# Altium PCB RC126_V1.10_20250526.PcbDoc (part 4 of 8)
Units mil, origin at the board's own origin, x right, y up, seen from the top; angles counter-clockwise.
Board outline 6299.62 x 3544.12 mil, 4 copper layers (Top, GND, Power, Bottom), stack 35.4 mil thick; 509 components, 417 nets, 1867 pads, 2150 vias.
Unrouted connection lines stored in the file: 1451.
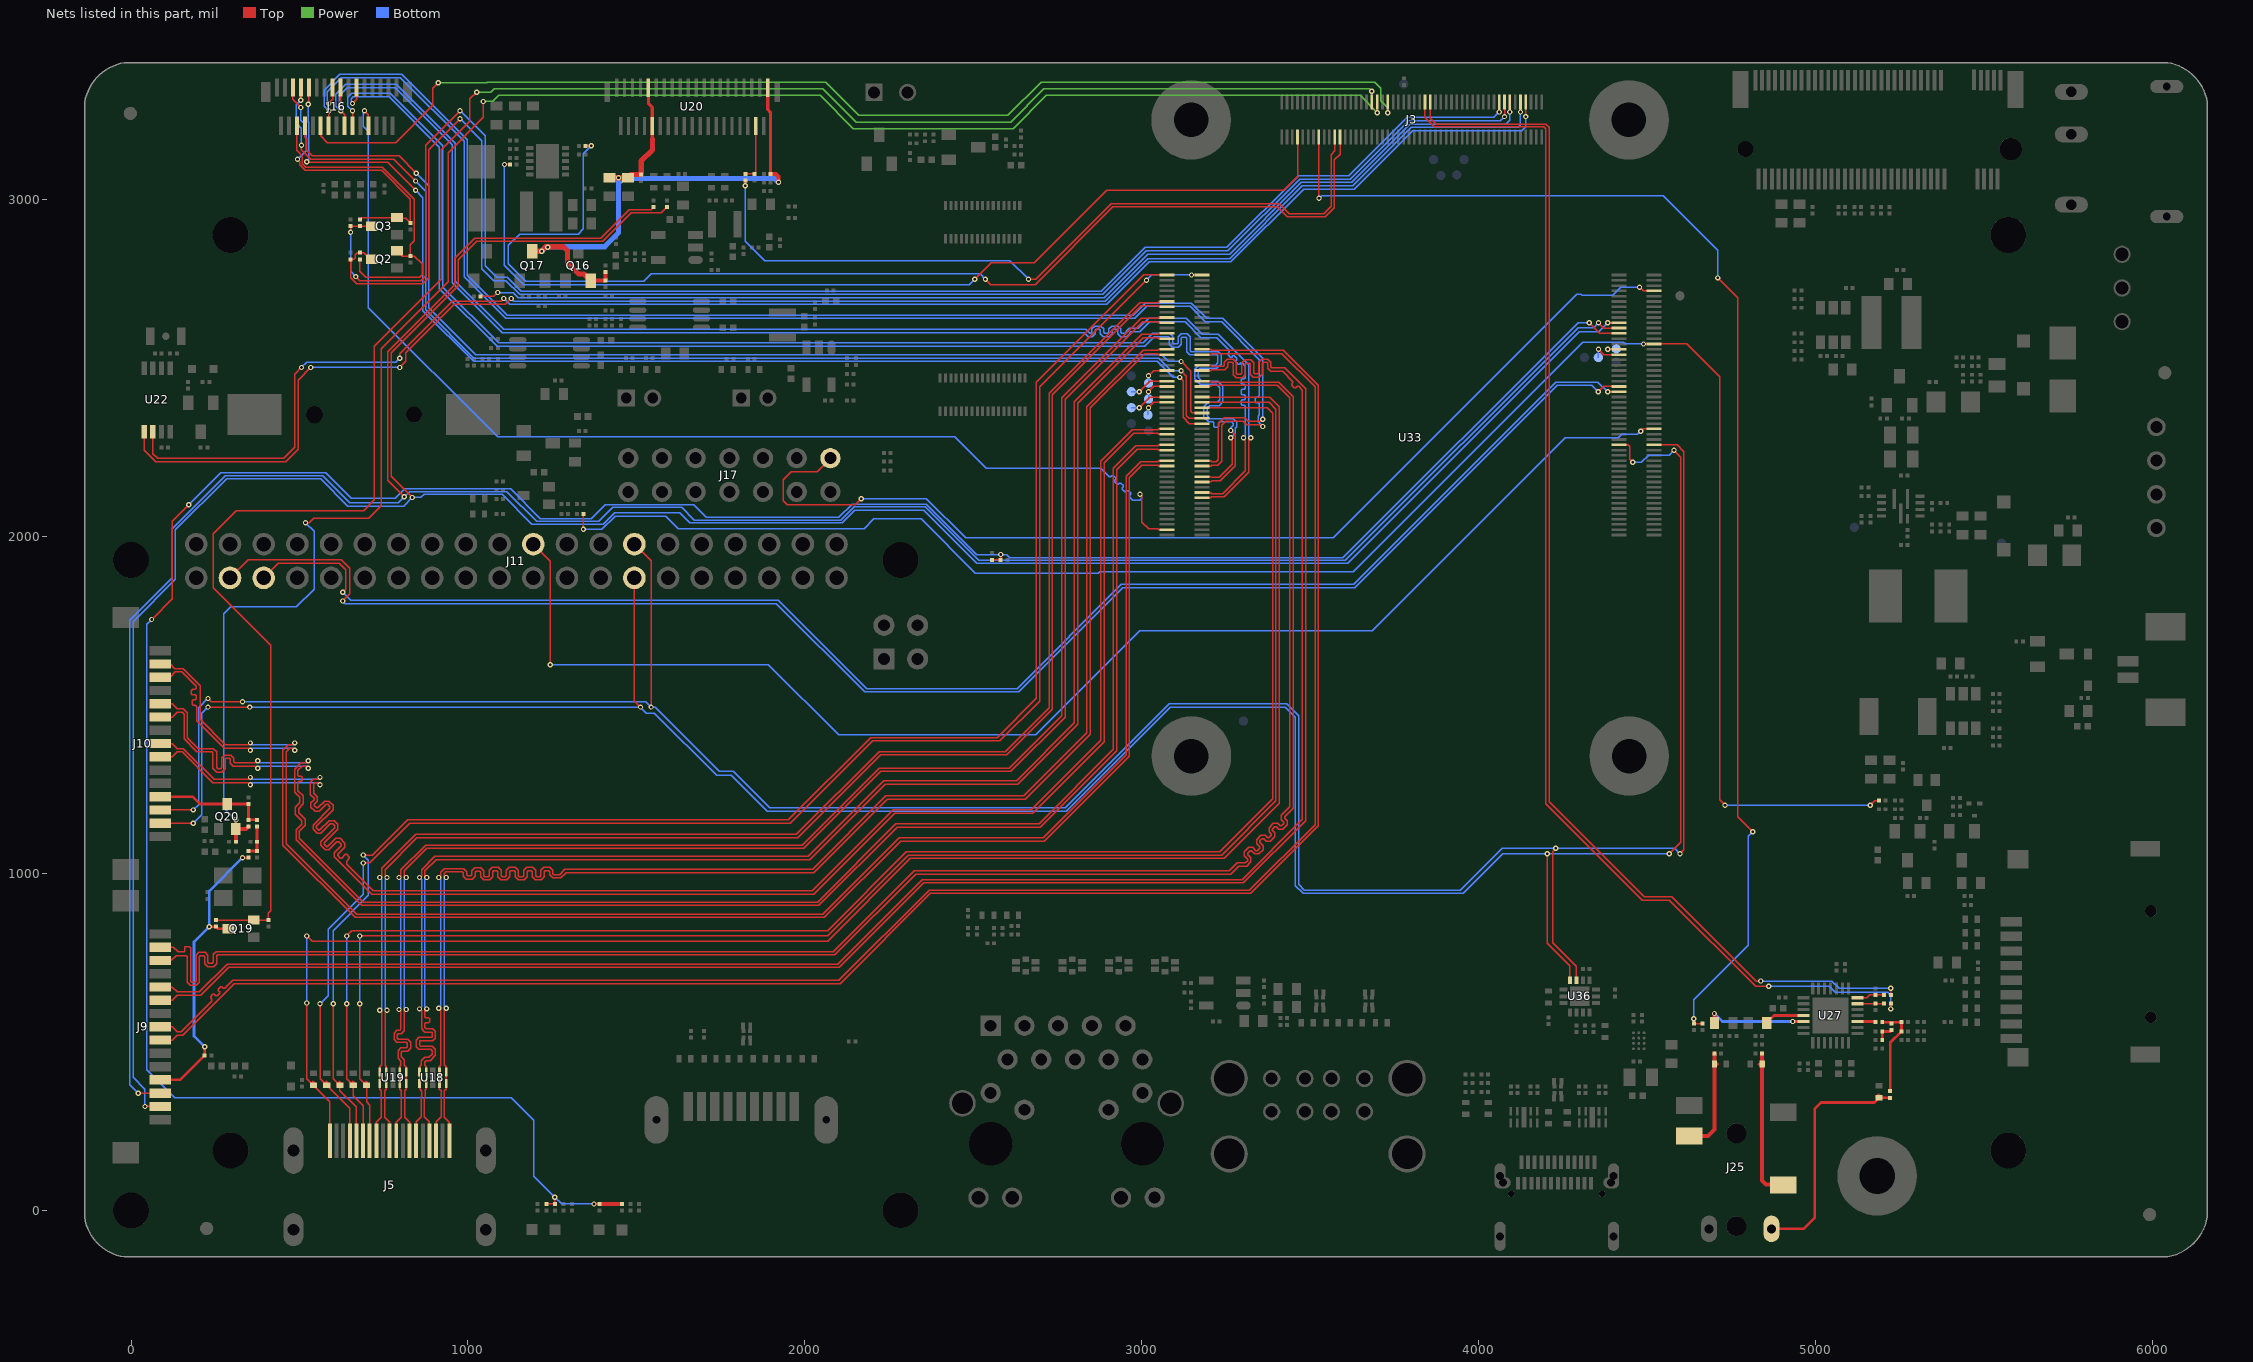
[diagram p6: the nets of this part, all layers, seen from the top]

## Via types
v1: diameter 15.75, hole 7.87, Top to Bottom, 2047 vias
v2: diameter 19.68, hole 11.81, Top to Bottom, 103 vias

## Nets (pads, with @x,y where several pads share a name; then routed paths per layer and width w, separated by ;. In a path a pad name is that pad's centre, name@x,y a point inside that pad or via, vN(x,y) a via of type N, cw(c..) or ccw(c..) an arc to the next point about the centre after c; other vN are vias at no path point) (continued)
GPIO3_D6_1V8: R326.1 R356.1 U33.73 | length 5594.9
  Top w3.94: v1(1342.52,2021.65) R356.1@1342.52,2066.93 ; v1(4488.58,2571.65) U33.73@4520.08,2571.65 4617.32,2571.65 4714.57,2474.41 4714.57,1218.5 v1(4730.32,1202.76) ; v1(5161.42,1202.76) 5175.2,1216.54 R326.1@5187.01,1216.54
  Bottom w3.94: v1(1342.52,2021.65) 1397.64,2021.65 1437.01,2061.02 1586.61,2061.02 1624.02,2023.62 2175.2,2023.62 2204.72,2053.15 2344.49,2053.15 2505.91,1891.73 2870.2,1891.73 2874.14,1895.67 3627.13,1895.67 4308.23,2576.77 4428.78,2576.77 4433.9,2571.65 v1(4488.58,2571.65) ; v1(4730.32,1202.76) v1(5161.42,1202.76)
GPIO_VREF: R214.1 R215.1 R216.2 R219.1 R224.1 R225.2 U33.78 | length 8265.5
  Top w3.94: v1(61.02,1753.94) 122.05,1814.96 122.05,2045.28 v1(171.26,2094.49) ; R219.1@1232.28,19.69 R216.2@1257.87,19.69 v1(1257.87,39.37) ; v1(1374.02,19.69) R224.1@1389.76,19.69 ; R215.1@2555.12,1931.1 R214.1@2580.71,1931.1 v1(2580.71,1946.85) ; v1(4327.17,2634.65) 4358.66,2603.15 U33.78@4415.35,2603.15
  Top w11.81: R224.1@1389.76,19.69 R225.2@1456.69,19.69
  Bottom w3.94: v1(61.02,1753.94) 47.24,1740.16 47.24,417.32 129.92,334.65 1127.95,334.65 1194.88,267.72 1194.88,102.36 v1(1257.87,39.37) 1277.56,19.69 v1(1374.02,19.69) ; v1(171.26,2094.49) 265.75,2188.98 578.13,2188.98 652.93,2114.17 784.02,2114.17 811.58,2141.73 1126.35,2141.73 1214.93,2053.15 1366.38,2053.15 1407.72,2094.49 1669.88,2094.49 1707.28,2057.09 2100.92,2057.09 2140.29,2096.46 2360.24,2096.46 2509.84,1946.85 v1(2580.71,1946.85) 2598.12,1946.85 2607.96,1937.01 3596.46,1937.01 4294.09,2634.65 v1(4327.17,2634.65)
HDMI_TX0N: J5.9 U19.4 U19.7 U33.184 | length 4399.1
  Top w3.94: J5.9@787.09,207.82 787.09,261.5 802.16,276.57 802.16,355.31 797.24,360.24 U19.4@797.24,376.48 U19.7@797.24,410.92 797.24,427.17 801.18,431.11 801.18,443.83 792.32,452.69 792.32,474.55 801.04,483.27 816.93,483.27 819.88,486.22 819.88,496.06 816.93,499.02 789.23,499.02 780.51,507.73 780.51,525.73 789.23,534.45 798.23,534.45 801.18,537.4 801.18,590.55 v1(795.28,596.46) ; v1(795.28,988.19) 801.18,994.09 801.18,1011.81 874.02,1084.65 1992.13,1084.65 2220.47,1312.99 2606.3,1312.99 2761.81,1468.5 2761.81,2411.42 2997.83,2647.44 3046.26,2647.44 3049.21,2650.39 U33.184@3074.8,2650.39
  Bottom w3.94: v1(795.28,596.46) 801.18,602.36 801.18,982.28 v1(795.28,988.19)
HDMI_TX0P: J5.7 U19.5 U19.6 U33.182 | length 4383.4
  Top w3.94: v1(816.93,596.46) 811.02,590.55 811.02,533.32 802.31,524.61 793.31,524.61 790.35,521.65 790.35,511.81 793.31,508.86 821.01,508.86 829.72,500.14 829.72,482.14 821.01,473.43 805.12,473.43 802.17,470.47 802.17,456.76 811.02,447.9 811.02,431.1 816.93,425.2 U19.6@816.93,410.92 U19.5@816.93,376.48 816.93,360.24 812.01,355.31 812.01,276.58 826.46,262.13 J5.7@826.46,207.82 ; v1(816.93,988.19) 811.02,994.09 811.02,1007.73 878.09,1074.8 1996.2,1074.8 2224.55,1303.15 2610.38,1303.15 2771.65,1464.43 2771.65,2407.34 3001.91,2637.6 3046.26,2637.6 3049.21,2634.65 U33.182@3074.8,2634.65
  Bottom w3.94: v1(816.93,596.46) 811.02,602.36 811.02,982.28 v1(816.93,988.19)
HDMI_TX1N: J5.6 U18.1 U18.10 U33.178 | length 4383.8
  Top w3.94: J5.6@846.14,207.82 846.14,263.46 860.9,278.22 860.9,337.28 863.19,339.57 863.19,354.34 856.3,361.22 U18.1@856.3,376.48 U18.10@856.3,410.92 856.3,427.17 861.22,432.09 861.22,443.9 872.05,454.72 883.86,454.72 893.7,464.57 893.7,474.41 889.76,478.35 861.08,478.35 854.19,478.35 846.46,486.08 846.46,506.05 854.19,513.78 859.11,513.78 891.73,513.78 893.7,515.75 893.7,527.56 891.73,529.53 871.91,529.53 862.2,539.23 862.2,592.52 v1(856.3,598.43) ; v1(856.3,988.19) 862.2,994.09 862.2,1011.81 901.57,1051.18 2009.84,1051.18 2234.25,1275.59 2627.81,1275.59 2799.21,1446.99 2799.21,2399.61 2999.8,2600.2 3046.26,2600.2 3049.21,2603.15 U33.178@3074.8,2603.15
  Bottom w3.94: v1(856.3,598.43) 862.2,604.33 862.2,982.28 ; v1(856.3,988.19) 862.2,982.28 ; v1@862.2,983.59 862.2,982.28
HDMI_TX1P: J5.4 U18.2 U18.9 U33.176 | length 4385.2
  Top w3.94: v1(877.95,598.43) 872.05,592.52 872.05,574.8 874.02,572.83 881.89,572.83 885.83,568.9 885.83,561.02 881.89,557.09 874.02,557.09 872.05,555.12 872.05,543.31 875.98,539.37 895.81,539.37 903.54,531.64 903.54,511.67 895.81,503.94 858.27,503.94 856.3,501.97 856.3,490.16 858.27,488.19 893.84,488.19 903.54,478.49 903.54,460.49 887.94,444.88 876.12,444.88 871.06,439.82 871.06,432.09 875.99,427.17 U18.9@875.99,410.92 U18.2@875.99,376.48 875.99,361.22 873.03,358.27 873.03,335.49 870.74,333.2 870.74,278.86 885.51,264.1 J5.4@885.51,207.82 ; v1(877.95,988.19) 872.05,994.09 872.05,1007.73 905.65,1041.34 2013.92,1041.34 2238.33,1265.75 2631.89,1265.75 2809.06,1442.91 2809.06,2395.53 3003.88,2590.35 3046.26,2590.35 3049.21,2587.4 U33.176@3074.8,2587.4
  Bottom w3.94: v1(877.95,598.43) 872.05,604.33 872.05,982.28 v1(877.95,988.19)
HDMI_TX2N: J5.3 U18.4 U18.7 U33.172 | length 4399.2
  Top w3.94: J5.3@905.2,207.82 905.2,263.46 920.27,278.54 920.27,355.31 915.35,360.24 U18.4@915.35,376.48 U18.7@915.35,410.92 915.35,427.17 919.29,431.11 919.29,594.49 v1(913.39,600.39) ; v1(913.39,988.19) 919.29,994.09 919.29,1003.94 930.12,1014.76 987.34,1014.76 996.06,1006.05 996.06,996.06 999.02,993.11 1008.86,993.11 1011.81,996.06 1011.81,1008.01 1020.53,1016.73 1038.53,1016.73 1047.24,1008.01 1047.24,994.09 1050.2,991.14 1060.04,991.14 1062.99,994.09 1062.99,1009.98 1071.71,1018.7 1089.71,1018.7 1098.43,1009.98 1098.43,994.09 1101.38,991.14 1111.22,991.14 1114.17,994.09 1114.17,1009.98 1122.89,1018.7 1140.89,1018.7 1149.61,1009.98 1149.61,994.09 1152.56,991.14 1162.4,991.14 1165.35,994.09 1165.35,1009.98 1174.07,1018.7 1192.07,1018.7 1200.79,1009.98 1200.79,994.09 1203.74,991.14 1213.58,991.14 1216.54,994.09 1216.54,1009.98 1225.25,1018.7 1243.25,1018.7 1251.97,1009.98 1251.97,1000 1254.92,997.05 1271.58,997.05 1287.33,1012.8 2022.64,1012.8 2240.16,1230.31 2267.72,1230.31 2649.61,1230.32 2836.61,1417.32 2836.61,2385.83 3003.74,2552.95 3046.26,2552.95 3049.21,2555.91 U33.172@3074.8,2555.91
  Bottom w3.94: v1(913.39,600.39) 919.29,606.3 919.29,982.52 913.63,988.19 v1(913.39,988.19)
HDMI_TX2P: J5.1 U18.5 U18.6 U33.170 | length 4383.5
  Top w3.94: v1(935.04,600.39) 929.13,594.49 929.13,433.07 935.04,427.17 U18.6@935.04,410.92 U18.5@935.04,376.48 935.04,360.24 930.12,355.31 930.12,276.58 944.57,262.13 J5.1@944.57,207.82 ; v1(935.04,988.19) 929.13,994.09 929.13,999.86 934.19,1004.92 983.27,1004.92 986.22,1001.97 986.22,991.99 994.94,983.27 1012.94,983.27 1021.65,991.99 1021.65,1003.94 1024.61,1006.89 1034.45,1006.89 1037.4,1003.94 1037.4,990.02 1046.12,981.3 1064.12,981.3 1072.83,990.02 1072.83,1005.91 1075.79,1008.86 1085.63,1008.86 1088.58,1005.91 1088.58,990.02 1097.3,981.3 1115.3,981.3 1124.02,990.02 1124.02,1005.91 1126.97,1008.86 1136.81,1008.86 1139.76,1005.91 1139.76,990.02 1148.48,981.3 1166.48,981.3 1175.2,990.02 1175.2,1005.91 1178.15,1008.86 1187.99,1008.86 1190.94,1005.91 1190.94,990.02 1199.66,981.3 1217.66,981.3 1226.38,990.02 1226.38,1005.91 1229.33,1008.86 1239.17,1008.86 1242.13,1005.91 1242.13,995.92 1250.84,987.2 1275.66,987.2 1291.41,1002.95 2026.71,1002.95 2244.23,1220.47 2653.68,1220.47 2846.46,1413.25 2846.46,2381.75 3007.82,2543.11 3046.26,2543.11 3049.21,2540.16 U33.170@3074.8,2540.16
  Bottom w3.94: v1(935.04,600.39) 929.13,606.3 929.13,982.52 929.37,982.52 v1(935.04,988.19)
HDMI_TX3N: J5.12 U19.1 U19.10 U33.190 | length 4402.4
  Top w3.94: J5.12@728.03,207.82 728.03,261.49 743.11,276.58 743.11,355.31 738.19,360.24 U19.1@738.19,376.48 U19.10@738.19,410.92 738.19,427.17 744.09,433.07 744.09,588.58 v1(738.19,594.49) ; v1(738.19,988.19) 744.09,994.09 744.09,1015.75 844.49,1116.14 1974.41,1116.14 2220.47,1362.2 2594.49,1362.2 2724.41,1492.13 2724.41,2425.2 2993.9,2694.68 3046.26,2694.68 3049.21,2697.64 U33.190@3074.8,2697.64
  Bottom w3.94: v1(738.19,594.49) 744.09,600.39 744.09,982.28 v1(738.19,988.19)
HDMI_TX3P: J5.10 U19.2 U19.9 U33.188 | length 4385
  Top w3.94: v1(759.84,594.49) 753.94,588.58 753.94,431.11 757.88,427.17 U19.9@757.88,410.92 U19.2@757.88,376.48 757.88,360.24 752.96,355.31 752.96,276.57 767.4,262.13 J5.10@767.4,207.82 ; v1(759.84,988.19) 753.94,994.09 753.94,1011.67 848.56,1106.3 1978.49,1106.3 2224.55,1352.36 2598.57,1352.36 2734.25,1488.05 2734.25,2421.12 2997.97,2684.84 3046.26,2684.84 3049.21,2681.89 U33.188@3074.8,2681.89
  Bottom w3.94: v1(759.84,594.49) 753.94,600.39 753.94,982.28 v1(759.84,988.19)
HDMI_TX_CEC_PORT: D14.1 J5.13 U33.151 | length 4893.1
  Top w3.94: v1(679.13,614.17) 679.13,391.73 D14.1@698.82,372.05 698.82,322.83 708.66,312.99 708.66,208.13 J5.13@708.35,207.82 ; v1(679.13,814.96) 2066.93,814.96 2307.09,1055.12 3236.22,1055.12 3397.64,1216.54 3397.64,2377.95 3377.17,2398.43 U33.151@3178.74,2398.43
  Bottom w3.94: v1(679.13,614.17) v1(679.13,814.96)
HDMI_TX_SCL_PORT: D12.1 J5.15 U33.200 | length 4574.3
  Top w3.94: v1(600.39,614.17) 600.39,391.73 D12.1@620.08,372.05 620.08,356.3 668.98,307.4 J5.15@668.98,207.82 ; v1(688.98,1055.12) 716.54,1055.12 820.87,1159.45 1950.79,1159.45 2194.88,1403.54 2570.87,1403.54 2687.01,1519.69 2687.01,2458.66 3004.72,2776.38 U33.200@3074.8,2776.38
  Bottom w3.94: v1(600.39,614.17) 600.39,830.71 704.72,935.04 704.72,1039.37 v1(688.98,1055.12)
HDMI_TX_SDA_PORT: D11.1 J5.16 U33.199 | length 4671.9
  Top w3.94: v1(561.02,614.17) 561.02,391.73 D11.1@580.71,372.05 649.29,303.47 J5.16@649.29,207.82 ; v1(688.98,1031.5) 708.66,1031.5 826.77,1149.61 1956.69,1149.61 2200.79,1393.7 2578.74,1393.7 2696.85,1511.81 2696.85,2444.09 v1(3013.39,2760.63) ; v1(3147.24,2776.38) U33.199@3178.74,2776.38
  Bottom w3.94: v1(561.02,614.17) 584.65,637.8 584.65,834.65 688.98,938.98 v1(688.98,1031.5) ; v1(3013.39,2760.63) 3029.13,2776.38 v1(3147.24,2776.38)
HDMITX_HPDIN/HDMITX_SBDN: D9.1 J5.19 U33.153 | length 5115.1
  Top w3.94: v1(521.65,616.14) 521.65,391.73 D9.1@541.34,372.05 590.24,323.15 J5.19@590.24,207.82 ; v1(521.65,814.96) 537.4,799.21 2066.93,799.21 2312.99,1045.28 3244.09,1045.28 3407.48,1208.66 3407.48,2385.83 3379.13,2414.17 U33.153@3178.74,2414.17
  Bottom w3.94: v1(521.65,616.14) v1(521.65,814.96)
HDMITX_SBDP: D10.1 J5.14 U33.149 | length 4903.8
  Top w3.94: v1(639.76,614.17) 639.76,391.73 D10.1@659.45,372.05 659.45,340.55 688.66,311.34 J5.14@688.66,207.82 ; v1(639.76,814.96) 655.51,830.71 2066.93,830.71 2301.18,1064.96 3230.32,1064.96 3387.8,1222.44 3387.8,2366.14 3371.26,2382.68 U33.149@3178.74,2382.68
  Bottom w3.94: v1(639.76,614.17) v1(639.76,814.96)
HP_DET_L: C1.1 J3.86 R19.1 | length 3872.1
  Top w3.94: J3.86@3524.81,3185.83 3524.81,3181.6 3524.8,3004.72 v1(3525.59,3003.94) ; v1(4637.8,568.9) C1.1@4637.8,555.12 R19.1@4663.39,555.12 ; v1(4708.66,2767.72) 4767.72,2708.66 4767.72,1169.29 v1(4812.99,1124.02)
  Bottom w3.94: v1(3525.59,3003.94) 3533.46,3011.81 4547.24,3011.81 4708.66,2850.39 v1(4708.66,2767.72) ; v1(4637.8,568.9) 4637.8,625.98 4799.21,787.4 4799.21,1110.24 v1(4812.99,1124.02)
HP_GND: C248.2 C276.2 R26.1 | length 54.8
  Top w7.87: R26.1@5196.85,505.91 C248.2@5196.85,531.5 5220.47,531.5 C276.2@5224.41,535.43
HPOUT_L: C275.1 U27.12 | length 301.1
  Top w7.87: v1(4931.1,561.02) U27.12@4962.6,561.02
  Top w11.81: C275.1@4698.82,557.09 v1(4698.82,584.65)
  Bottom w7.87: v1(4698.82,584.65) 4722.44,561.02 v1(4931.1,561.02)
HPOUT_L_C: D32.1 FB16.2 J25.3 | length 309
  Top w11.81: J25.3@4624.02,221.26 4679.92,221.26 4698.82,240.16 D32.1@4698.82,435.04 FB16.2@4698.82,466.54
HPOUT_R: C278.1 U27.11 | length 117.2
  Top w7.87: C278.1@4854.33,557.09 4875.98,578.74 U27.11@4962.6,578.74
HPOUT_R_C: D7.1 FB17.2 J25.6 | length 446.3
  Top w11.81: FB17.2@4840.55,466.54 D7.1@4840.55,435.04 4840.55,88.58 4852.36,76.77 4902.36,76.77 J25.6@4903.54,75.59
HSON: P7.1 U33.154 | length 119.3
  Top w3.94: v1(2991.73,2382.68) 3023.23,2414.17 U33.154@3074.8,2414.17
  Bottom w3.94: P7.1@2968.5,2382.68 v1(2991.73,2382.68)
HSON_CLK: P9.1 U33.160 | length 119.3
  Top w3.94: v1(2991.73,2429.92) 3023.23,2461.42 U33.160@3074.8,2461.42
  Bottom w3.94: P9.1@2968.5,2429.92 v1(2991.73,2429.92)
HSOP: P6.1 U33.152 | length 84.3
  Top w3.94: v1(3019.29,2382.68) 3035.04,2398.43 U33.152@3074.8,2398.43
  Bottom w3.94: P6.1@3017.72,2361.02 3017.72,2381.1 v1(3019.29,2382.68)
HSOP_CLK: P8.1 U33.158 | length 83.9
  Top w3.94: v1(3019.29,2429.92) 3035.04,2445.67 U33.158@3074.8,2445.67
  Bottom w3.94: v1(3019.29,2429.92) 3019.68,2429.53 P8.1@3019.68,2408.27
I2C0_SCL_M1_TP: J9.3 R256.1 U33.80 | length 8123.9
  Top w3.94: v1(21.65,348.43) J9.3@86.61,348.4 ; v1(811.02,2118.11) 761.81,2167.32 761.81,2549.21 960.63,2748.03 960.63,2826.77 1019.69,2885.83 1393.7,2885.83 1478.35,2970.47 1543.31,2970.47 R256.1@1551.18,2978.35 ; v1(4354.72,2634.65) 4370.47,2618.9 U33.80@4415.35,2618.9
  Bottom w3.94: v1(21.65,348.43) -3.94,374.02 -3.94,1751.97 122.05,1877.95 122.05,2023.62 279.53,2181.1 568.9,2181.1 649.61,2100.39 793.31,2100.39 v1(811.02,2118.11) 826.77,2133.86 1115.37,2133.86 1203.96,2045.28 1387.8,2045.28 1429.13,2086.61 1633.86,2086.61 1671.26,2049.21 2106.3,2049.21 2145.67,2088.58 2356.79,2088.58 2516.24,1929.13 3603.22,1929.13 4294.17,2620.08 4340.16,2620.08 v1(4354.72,2634.65)
I2C0_SDA_M1_TP: J9.2 R258.1 U33.82 | length 8154.6
  Top w3.94: v1(41.34,309.06) 41.38,309.1 J9.2@86.61,309.1 ; v1(834.65,2116.14) 771.65,2179.13 771.65,2545.28 970.47,2744.09 970.47,2820.87 1025.59,2875.98 1399.61,2875.98 1484.25,2960.63 1572.83,2960.63 R258.1@1590.55,2978.35 ; v1(4382.28,2634.65) U33.82@4415.35,2634.65
  Bottom w3.94: v1(41.34,309.06) 41.34,360.24 5.91,395.67 5.91,1748.03 131.89,1874.02 131.89,2019.69 283.46,2171.26 562.99,2171.26 643.7,2090.55 809.06,2090.55 v1(834.65,2116.14) 860.34,2116.14 870.18,2125.98 1101.23,2125.98 1189.82,2037.4 1401.57,2037.4 1435.04,2070.87 1627.95,2070.87 1657.48,2041.34 2110.24,2041.34 2147.64,2078.74 2352.36,2078.74 2509.84,1921.26 3610.42,1921.26 4297.43,2608.27 4355.91,2608.27 v1(4382.28,2634.65)
I2C2_SCL_M0_CC_RTC: J3.7 U22.6 | length 4775.2
  Top w3.94: U22.6@64.96,2311.02 64.96,2246.06 78.74,2232.28 452.76,2232.28 486.22,2265.75 486.22,2482.28 v1(505.91,2501.97) ; v1(797.24,2529.53) 797.24,2543.31 952.76,2698.82 1098.43,2698.82 v1(1106.3,2706.69) ; v1(4138.98,3246.46) 4138.98,3277.5 J3.7@4138.98,3289.77
  Bottom w3.94: v1(505.91,2501.97) 521.65,2517.72 785.43,2517.72 v1(797.24,2529.53) ; v1(1106.3,2706.69) 1124.02,2688.98 2895.67,2688.98 3021.65,2814.96 3263.78,2814.96 3480.32,3031.5 3629.92,3031.5 3803.15,3204.72 4127.17,3204.72 4138.98,3216.54 v1(4138.98,3246.46)
I2C2_SDA_M0_CC_RTC: J3.9 U22.5 | length 4777
  Top w3.94: U22.5@39.37,2311.02 39.37,2255.91 72.83,2222.44 458.66,2222.44 496.06,2259.84 496.06,2464.57 v1(533.46,2501.97) ; v1(797.24,2501.97) 814.96,2519.69 814.96,2545.28 958.66,2688.98 1110.24,2688.98 v1(1127.95,2706.69) ; v1(4123.23,3260.24) 4123.23,3279.9 J3.9@4123.23,3289.77
  Bottom w3.94: v1(533.46,2501.97) v1(797.24,2501.97) ; v1(1127.95,2706.69) 1135.83,2698.82 2891.73,2698.82 3017.72,2824.8 3259.84,2824.8 3476.38,3041.34 3625.98,3041.34 3799.21,3214.57 4117.32,3214.57 4123.23,3220.47 v1(4123.23,3260.24)
I2C3_SCL_M0_AUDIO: J3.43 R29.1 | length 3676.8
  Top w3.94: J3.43@3855.52,3289.77 3855.52,3274.9 3855.51,3242.13 3873.23,3224.41 4198.82,3224.41 4208.66,3214.57 4208.66,1212.6 4490.16,931.1 4572.83,931.1 4822.83,681.1 v1(4836.61,681.1) ; R29.1@5222.44,639.76 v1(5222.44,659.45)
  Bottom w3.94: v1(4836.61,681.1) 5047.24,681.1 5068.9,659.45 v1(5222.44,659.45)
I2C3_SDA_M0_AUDIO: J3.45 R109.1 | length 3736.9
  Top w3.94: J3.45@3839.77,3289.77 3839.77,3278.8 3839.76,3244.09 3867.32,3216.54 4192.91,3216.54 4198.82,3210.63 4198.82,1206.69 4484.25,921.26 4564.96,921.26 4820.87,665.35 v1(4860.24,665.35) ; v1(5222.44,598.43) R109.1@5222.44,614.17
  Bottom w3.94: v1(4860.24,665.35) 5039.37,665.35 5057.09,647.64 5212.6,647.64 5222.44,637.8 v1(5222.44,598.43)
I2C4_SCL_M3_1V8: P27.1 U33.72 | length 58.8
  Top w3.94: v1(4382.28,2555.91) U33.72@4415.35,2555.91
  Bottom w3.94: v1(4382.28,2555.91) 4406.3,2555.91 P27.1@4407.48,2557.09
I2C4_SDA_M3_1V8: P26.1 U33.70 | length 91.7
  Top w3.94: v1(4354.72,2555.91) 4370.47,2540.16 U33.70@4415.35,2540.16
  Bottom w3.94: P26.1@4354.33,2531.5 4354.72,2531.89 v1(4354.72,2555.91)
I2C5_SCL_M3_1V8: J16.24 U33.147 | length 3337.9
  Top w3.94: J16.24@515.75,3219.5 515.75,3187.01 521.65,3181.11 521.65,3145.87 537.6,3129.92 795.28,3129.92 v1(846.46,3078.74) ; v1(3116.14,2519.69) 3144.49,2491.34 3144.49,2372.05 3149.61,2366.93 U33.147@3178.74,2366.93
  Bottom w3.94: v1(846.46,3078.74) 883.86,3041.34 883.86,2679.13 1023.62,2539.37 3059.06,2539.37 3078.74,2519.69 v1(3116.14,2519.69)
I2C5_SDA_M3_1V8: J16.25 U33.145 | length 3475.1
  Top w3.94: v1(503.94,3295.28) J16.25@503.94,3332.68 ; v1(505.91,3161.42) 505.91,3147.64 533.46,3120.08 779.53,3120.08 v1(844.49,3055.12) ; v1(3116.14,2492.13) 3131.89,2476.38 3131.89,2359.06 3139.76,2351.18 U33.145@3178.74,2351.18
  Bottom w3.94: v1(503.94,3295.28) 490.16,3281.5 490.16,3227.46 505.91,3211.71 v1(505.91,3161.42) ; v1(844.49,3055.12) 874.02,3025.59 874.02,2673.23 1017.72,2529.53 3049.21,2529.53 3086.61,2492.13 v1(3116.14,2492.13)
I2C6_SCL_M3: J10.3 J11.28 U33.35 U36.6 | length 7880.9
  Top w3.94: J10.3@86.61,1188.95 v1(185.04,1188.98) ; v1(228.35,1519.69) 238.19,1509.84 v1(330.71,1509.84) ; J11.28@1493.7,1977.56 1543.31,1927.95 v1(1543.31,1494.09) ; v1(4228.35,1074.8) 4218.5,1064.96 4218.5,795.28 4289.37,724.41 U36.6@4289.37,683.46 ; U33.35@4520.08,2272.44 4587.8,2272.44 4608.27,2251.97 4608.27,1070.87 v1(4596.46,1059.06)
  Bottom w3.94: v1(185.04,1188.98) 200.79,1204.72 200.79,1492.13 v1(228.35,1519.69) ; v1(330.71,1509.84) 1527.56,1509.84 v1(1543.31,1494.09) 1555.12,1494.09 1746.06,1303.15 1787.4,1303.15 1895.67,1194.88 2771.65,1194.88 3080.71,1503.94 3429.13,1503.94 3464.57,1468.5 3464.57,968.5 3482.28,950.79 3944.88,950.79 4068.9,1074.8 v1(4228.35,1074.8) 4580.71,1074.8 v1(4596.46,1059.06)
I2C6_SDA_M3: J10.2 J11.27 U33.36 U36.7 | length 7859.1
  Top w3.94: J10.2@86.61,1149.65 185,1149.65 v1(185.04,1149.61) ; v1(228.35,1494.09) v1(352.36,1494.09) ; J11.27@1493.7,1877.56 1493.7,1512.2 v1(1511.81,1494.09) ; v1(4202.76,1059.06) 4202.76,793.31 4269.69,726.38 U36.7@4269.69,683.46 ; U33.36@4415.35,2272.44 4442.13,2272.44 4446.85,2267.72 4446.85,2230.32 v1(4456.69,2220.47) ; v1(4564.96,1059.06) 4598.43,1092.52 4598.43,2236.22 v1(4578.74,2255.91)
  Bottom w3.94: v1(185.04,1149.61) 210.63,1175.2 210.63,1476.38 v1(228.35,1494.09) ; v1(352.36,1494.09) v1(1511.81,1494.09) 1529.53,1476.38 1553.15,1476.38 1738.19,1291.34 1781.5,1291.34 1887.8,1185.04 2775.59,1185.04 3084.65,1494.09 3425.2,1494.09 3454.72,1464.57 3454.72,964.57 3478.35,940.94 3952.76,940.94 4070.87,1059.06 v1(4202.76,1059.06) v1(4564.96,1059.06) ; v1(4456.69,2220.47) 4482.28,2220.47 4503.94,2242.13 4564.96,2242.13 v1(4578.74,2255.91)
I2C8_SCL_M1: J11.5 U33.56 | length 4635.6
  Top w3.94: J11.5@393.7,1877.56 437.4,1921.26 618.11,1921.26 637.8,1901.57 637.8,1844.49 v1(627.95,1834.65) ; v1(4381.89,2429.92) U33.56@4415.35,2429.92
  Bottom w3.94: v1(627.95,1834.65) 651.57,1811.02 1921.26,1811.02 2183.07,1549.21 2629.92,1549.21 2938.98,1858.27 3627.95,1858.27 4228.35,2458.66 4353.15,2458.66 v1(4381.89,2429.92)
I2C8_SDA_M1: J11.3 U33.58 | length 4784.3
  Top w3.94: J11.3@293.7,1877.56 347.24,1931.1 624.02,1931.1 649.61,1905.51 649.61,1830.71 v1(627.95,1809.06) ; v1(4354.33,2429.92) 4370.08,2445.67 U33.58@4415.35,2445.67
  Bottom w3.94: v1(627.95,1809.06) 635.83,1801.18 1915.35,1801.18 2177.17,1539.37 2633.86,1539.37 2942.91,1848.43 3631.89,1848.43 4232.28,2448.82 4335.43,2448.82 v1(4354.33,2429.92)
I2C_SCL_ES8388: C245.1 R29.2 U27.28 | length 82
  Top w3.94: U27.28@5124.02,631.89 5151.57,631.89 5159.45,639.76 C245.1@5177.17,639.76 R29.2@5202.76,639.76
I2C_SDA_ES8388: C246.1 R109.2 U27.27 | length 86.6
  Top w3.94: U27.27@5124.02,614.17 C246.1@5177.17,614.17 5206.69,614.17 R109.2@5202.76,614.17
INTB: P10.1 U33.164 | length 83.9
  Top w3.94: v1(3019.29,2477.17) 3035.04,2492.91 U33.164@3074.8,2492.91
  Bottom w3.94: v1(3019.29,2477.17) 3019.68,2476.77 P10.1@3019.68,2455.51
LCD_3V3: C182.1 C183.1 C184.1 Q16.2 Q17.3 R229.1 R232.1 R235.2 U20.1 U20.30 U20.31 | length 1902.1
  Top w9.84: U20.31@1535.43,3331.89 1535.43,3285.43 1547.24,3273.62 U20.30@1547.24,3218.71 1547.24,3179.13 ; U20.1@1889.76,3331.89 1889.76,3267.72 1897.64,3259.84 R229.1@1897.64,3076.77
  Top w11.81: Q16.2@1364.17,2759.84 R235.2@1407.48,2759.84 R232.1@1407.48,2785.43 ; R229.1@1897.64,3076.77 1913.39,3076.77 1921.26,3068.9 v1(1921.26,3051.18)
  Top w15: v1(1218.5,2846.46) 1218.5,2848.43 1230.32,2860.24 1283.46,2860.24 1295.28,2848.43 1295.28,2812.99 1328.74,2779.53 1344.48,2779.53 Q16.2@1364.17,2759.84
  Top w15.75: Q17.3@1190.94,2846.46 v1(1218.5,2846.46) ; C182.1@1419.29,3064.96 v1(1446.85,3064.96) C183.1@1474.41,3064.96 1484.25,3074.8 C184.1@1513.78,3074.8 1513.78,3114.17 1547.24,3147.64 1547.24,3179.13
  Bottom w15.75: v1(1218.5,2846.46) 1232.28,2860.24 1405.51,2860.24 1446.85,2901.57 1446.85,3049.21 ; v1(1446.85,3064.96) v1@1446.85,3062.99 ; v1(1921.26,3051.18) 1909.45,3062.99 1460.63,3062.99 ; 1446.85,3049.21 v1@1446.85,3062.99 ; 1446.85,3049.21 1460.63,3062.99 ; v1@1446.85,3062.99 1460.63,3062.99
  other v1: 1236.22,2858.27
LCD_LIGHT_EN: J3.78 R246.1 | length 3401
  Top w3.94: R246.1@1348.43,3159.45 v1(1366.14,3159.45) ; v1(2535.43,2763.78) 2551.18,2748.03 2683.53,2748.03 2913.84,2978.35 3401.57,2978.35 3431.1,2948.82 3543.31,2948.82 3570.87,2976.38 3570.87,3118.11 3587.8,3135.04 3587.8,3179.8 J3.78@3587.8,3185.83
  Bottom w3.94: v1(1366.14,3159.45) 1342.52,3135.83 1342.52,2913.39 1326.77,2897.64 1153.54,2897.64 1120.08,2864.17 1120.08,2809.06 1171.26,2757.87 1521.65,2757.87 1543.31,2779.53 2519.68,2779.53 v1(2535.43,2763.78)
LCD_PWM: J3.94 R247.1 | length 2942
  Top w3.94: v1(1108.27,3104.33) R247.1@1124.02,3104.33 ; v1(2503.94,2763.78) 2553.15,2812.99 2681.1,2812.99 2895.67,3027.56 3420.47,3027.56 3461.81,3068.9 3461.81,3181.4 J3.94@3461.82,3185.83
  Bottom w3.94: v1(1108.27,3104.33) 1108.27,2805.12 1165.35,2748.03 2488.19,2748.03 v1(2503.94,2763.78)
LCD_PWREN_H: J3.13 R262.1 | length 3337.8
  Top w3.94: R262.1@1037.4,2712.6 1076.77,2712.6 v1(1088.58,2724.41) ; v1(4091.73,3260.24) 4091.73,3276.2 J3.13@4091.74,3289.77
  Bottom w3.94: v1(1088.58,2724.41) 1133.86,2724.41 1149.54,2708.73 1163.32,2708.73 1163.39,2708.66 2887.8,2708.66 3017.72,2838.58 3259.84,2838.58 3472.44,3051.18 3622.05,3051.18 3795.28,3224.41 4079.92,3224.41 4091.73,3236.22 v1(4091.73,3260.24)
LCD_RESET: J3.80 R250.1 | length 2290
  Top w3.94: v1(1822.83,3041.34) R250.1@1822.83,3057.09 ; v1(2663.39,2763.78) 2685.04,2763.78 2909.45,2988.19 3407.48,2988.19 3437.01,2958.66 3539.37,2958.66 3561.02,2980.32 3561.02,3133.86 3572.05,3144.88 3572.05,3180.5 J3.80@3572.05,3185.83
  Bottom w3.94: v1(1822.83,3041.34) 1822.83,2875.98 1879.92,2818.9 2608.27,2818.9 v1(2663.39,2763.78)
LCD_RESET_1: R250.2 R251.1 U20.4 | length 171.1
  Top w3.94: R250.2@1822.83,3076.77 R251.1@1850.39,3076.77 1854.33,3080.71 U20.4@1854.33,3218.71
LIN1_ES8388: C247.1 U27.24 | length 54
  Top w7.87: U27.24@5124.02,561.02 5175.2,561.02 C247.1@5177.17,559.06
MASKROM: J17.14 U33.93 | length 3189.6
  Top w3.94: J17.14@2075.59,2232.68 2035.83,2192.91 1958.66,2192.91 1935.04,2169.29 1935.04,2106.3 1946.85,2094.49 2149.61,2094.49 v1(2167.32,2112.2) ; v1(4476.38,2740.16) 4487.4,2729.13 U33.93@4520.08,2729.13
  Bottom w3.94: v1(2167.32,2112.2) 2360.24,2112.2 2476.38,1996.06 3568.28,1996.06 4290.72,2718.5 4303.15,2718.5 4305.12,2716.54 4397.64,2716.54 4421.26,2740.16 v1(4476.38,2740.16)
MCLK: C195.1 R267.1 R268.1 R269.1 | length 98.4
  Top w7.87: R269.1@348.43,1066.93 R268.1@374.02,1066.93 C195.1@374.02,1094.49 R267.1@374.02,1139.76
MIC1P: D31.1 FB21.2 J25.5 | length 702.6
  Top w7.87: J25.5@4868.11,-54.33 4963.39,-54.33 4996.06,-21.65 4996.06,301.18 5015.75,320.87 5173.23,320.87 D31.1@5187.01,334.65 FB21.2@5220.47,334.65
MIC_INP_PHONE: C247.2 C276.1 FB21.1 R291.1 R305.1 | length 278.9
  Top w7.87: C247.2@5196.85,559.06 5220.47,559.06 C276.1@5224.41,555.12 5228.35,559.06 R305.1@5253.94,559.06 R291.1@5253.94,531.5 5220.47,498.03 FB21.1@5220.47,354.33
MIPI_CAM3_PDN2_1V8: J16.26 Q2.2 R9.1 R10.1 | length 1022.9
  Top w3.94: J16.26@492.12,3219.5 492.12,3145.91 507.87,3130.16 507.87,3106.5 517.91,3096.46 745.19,3096.46 840.55,3001.1 840.55,2877.71 828.74,2865.9 R9.1@828.74,2832.68 ; R10.1@679.13,2822.83 679.13,2787.4 696.85,2769.69 856.3,2769.69 864.17,2777.56 864.17,2809.06 840.55,2832.68 R9.1@828.74,2832.68 ; Q2.2@789.37,2848.42 805.12,2832.68 R9.1@828.74,2832.68
MIPI_CAM3_PDN_1V8: J16.23 U33.143 | length 3464.7
  Top w3.94: v1(521.65,3112.2) 521.65,3110.24 761.81,3110.24 v1(844.49,3027.56) ; v1(525.59,3283.46) 527.56,3285.44 J16.23@527.56,3332.68 ; v1(3112.2,2472.44) 3122.05,2462.6 3122.05,2354.33 3140.94,2335.43 U33.143@3178.74,2335.43
  Bottom w3.94: v1(521.65,3112.2) 527.56,3118.11 527.56,3228.35 525.59,3230.32 v1(525.59,3283.46) ; v1(844.49,3027.56) 866.14,3005.91 866.14,2669.97 1016.42,2519.69 3045.28,2519.69 3092.52,2472.44 v1(3112.2,2472.44)
MIPI_CAM3_PDN_3V3: J3.15 Q2.3 R8.1 R10.2 | length 4698.1
  Top w3.94: Q2.3@714.57,2822.83 710.63,2826.77 706.69,2826.77 690.94,2842.52 R10.2@679.13,2842.52 671.26,2842.52 665.35,2836.61 665.35,2826.77 661.42,2822.83 R8.1@651.57,2822.83 651.57,2767.72 669.29,2750 866.14,2750 883.86,2767.72 883.86,3147.64 v1(976.38,3240.16) ; v1(4075.98,3246.46) 4075.98,3278.4 J3.15@4075.99,3289.77
  Bottom w3.94: v1(976.38,3240.16) 1041.34,3175.2 1041.34,2795.28 1076.77,2759.84 1112.2,2759.84 1153.54,2718.5 2883.86,2718.5 3013.1,2847.75 3255.23,2847.75 3468.5,3061.02 3618.11,3061.02 3791.34,3234.25 4063.78,3234.25 v1(4075.98,3246.46)
MIPI_CAM3_RST_1V8: J16.27 Q3.2 R12.1 R13.1 | length 859.7
  Top w3.94: J16.27@480.31,3332.68 480.31,3297.25 v1(503.94,3273.62) ; v1(494.09,3120.08) 493.04,3119.02 500,3112.06 500,3103.24 516.62,3086.61 743.9,3086.61 828.74,3001.77 R12.1@828.74,2931.1 814.96,2944.88 791.34,2944.88 Q3.2@789.37,2946.85 685.04,2946.85 R13.1@679.13,2940.94
  Bottom w3.94: v1(494.09,3120.08) 519.69,3145.67 519.69,3220.47 503.94,3236.22 v1(503.94,3273.62)
MIPI_CAM3_RST_3V3: J3.17 Q3.3 R11.1 R13.2 | length 4750.5
  Top w3.94: v1(651.57,2903.54) R11.1@651.57,2921.26 R13.2@679.13,2921.26 Q3.3@714.57,2921.26 ; v1(667.32,2771.65) 679.13,2759.84 860.24,2759.84 874.02,2773.62 874.02,3161.42 v1(976.38,3263.78) ; v1(4060.24,3260.24) 4060.24,3276.1 J3.17@4060.24,3289.77
  Bottom w3.94: v1(651.57,2903.54) 651.57,2787.4 v1(667.32,2771.65) ; v1(976.38,3263.78) 1051.18,3188.98 1051.18,2803.15 1084.65,2769.69 1116.14,2769.69 1157.48,2728.35 2879.92,2728.35 3009.84,2858.27 3251.97,2858.27 3464.57,3070.87 3614.17,3070.87 3787.4,3244.09 4044.09,3244.09 v1(4060.24,3260.24)
MIPI_CSI0_CAM_CLKOUT_1V8: J3.63 Q20.2 R271.1 R272.1 | length 5602.8
  Top w3.94: Q20.2@311.02,1131.89 v1(311.02,1159.45) ; v1(517.72,2041.34) 529.1,2041.34 542.88,2055.12 706.02,2055.12 742.13,2091.23 742.13,2557.09 940.94,2755.91 940.94,3139.76 1045.28,3244.09 v1(1045.28,3291.34) ; v1(3698.03,3258.27) 3698.03,3279.6 J3.63@3698.04,3289.77
  Top w11.81: R271.1@311.02,1094.49 Q20.2@311.02,1131.89 340.55,1131.89 R272.1@348.43,1139.76
  Power w3.94: v1(1045.28,3291.34) 1072.83,3291.34 1090.55,3309.06 2045.28,3309.06 2143.7,3210.63 2618.11,3210.63 2716.54,3309.06 3647.24,3309.06 v1(3698.03,3258.27)
  Bottom w3.94: v1(311.02,1159.45) 275.59,1194.88 275.59,1771.65 295.28,1791.34 490.16,1791.34 543.31,1844.49 543.31,2015.75 v1(517.72,2041.34)
MIPI_CSI0_CAM_CLKOUT_3V3: J10.4 Q20.3 R267.2 R270.1 R272.2 | length 343.6
  Top w7.87: J10.4@86.61,1228.35 183.07,1228.35 204.73,1206.69 Q20.3@285.43,1206.69 R270.1@348.43,1206.69 ; R270.1@348.43,1206.69 R272.2@348.43,1159.45 R267.2@374.02,1159.45
MIPI_CSI1_CAM_CLKOUT_1V8: J3.65 Q19.2 R212.1 R266.1 | length 6008
  Top w3.94: R266.1@251.97,862.2 Q19.2@364.17,862.2 R212.1@407.48,862.2 407.48,881.99 415.35,889.86 415.35,1677.17 244.09,1848.43 244.09,2007.87 312.99,2076.77 690.27,2076.77 722.44,2108.94 722.44,2564.96 921.26,2763.78 921.26,3147.64 1005.91,3232.28 1005.91,3299.21 v1(1025.59,3318.9) ; J3.65@3682.29,3289.77 3682.29,3292.2 v1(3682.28,3321.26)
  Power w3.94: v1(1025.59,3318.9) 1067.91,3318.9 1077.76,3328.74 2053.15,3328.74 2151.57,3230.32 2610.24,3230.32 2708.66,3328.74 3674.8,3328.74 v1(3682.28,3321.26)
MIPI_CSI1_CAM_CLKOUT_3V3: J9.4 Q19.3 R211.1 R266.2 R269.2 | length 898.5
  Top w7.87: J9.4@86.61,387.8 145.67,387.8 R211.1@218.5,460.63 v1(218.5,486.22) ; v1(232.28,842.52) R266.2@251.97,842.52 257.87,836.61 Q19.3@289.37,836.61 ; v1(330.71,1047.24) R269.2@348.43,1047.24
  Bottom w7.87: v1(218.5,486.22) 187.01,517.72 187.01,797.24 v1(232.28,842.52) 232.28,948.82 v1(330.71,1047.24)
MIPI_CSI3_CAM_CLKOUT_1V8: J3.59 J16.20 | length 3490
  Top w3.94: J16.20@562.99,3219.5 562.99,3188.98 582.68,3169.29 785.43,3169.29 895.67,3279.53 895.67,3330.71 v1(911.42,3346.46) ; v1(3729.53,3258.27) J3.59@3729.53,3289.77
  Power w3.94: v1(911.42,3346.46) 1055.12,3346.46 1057.09,3348.43 2061.02,3348.43 2159.45,3250 2602.36,3250 2700.79,3348.43 3690.94,3348.43 3708.66,3330.71 3708.66,3293.31 3729.53,3272.44 v1(3729.53,3258.27)
MIPI_DPHY_CSI1_RX_CLKN: J10.8 U33.140 | length 4655.9
  Top w3.94: J10.8@86.61,1385.83 122.05,1385.83 136.81,1371.06 155.65,1371.06 247.19,1279.53 348.43,1279.53 v1(354.33,1285.43) ; 548.42,1184.85 546.38,1184.85 533.65,1197.58 533.65,1209.91 543.12,1219.37 543.12,1223.55 532.48,1234.18 532.48,1270.81 541.2,1279.53 541.34,1279.53 555.12,1279.53 v1(561.02,1285.43) ; 548.45,1184.85 556.7,1184.85 558.73,1184.88 579,1205.14 583.17,1205.14 590.13,1198.18 590.13,1194.01 540.32,1144.19 540.32,1131.86 553.04,1119.13 555.08,1119.13 563.37,1119.13 591.87,1147.64 598.43,1147.64 604.33,1141.73 604.33,1135.83 562.99,1094.49 562.99,1083.59 576.44,1070.15 578.47,1070.15 586.76,1070.15 611.1,1094.49 616.14,1094.49 624.02,1086.61 624.02,1082.68 603.35,1062.01 603.35,1050.13 714.5,938.98 2025.73,938.98 2265.89,1179.13 2675.2,1179.13 2887.8,1391.73 2887.8,2219.42 2975.27,2306.89 3046.26,2306.89 3049.21,2303.94 U33.140@3074.8,2303.94
  Bottom w3.94: v1(354.33,1285.43) 360.24,1279.53 555.12,1279.53 v1(561.02,1285.43)
MIPI_DPHY_CSI1_RX_CLKP: J10.7 U33.142 | length 4655.7
  Top w3.94: J10.7@86.61,1346.46 122.05,1346.46 136.81,1361.22 151.57,1361.22 243.11,1269.69 348.43,1269.69 v1(354.33,1263.78) ; v1(561.02,1263.78) 555.12,1269.69 545.28,1269.69 542.32,1266.73 542.32,1238.26 552.96,1227.62 552.96,1215.29 543.5,1205.83 543.5,1201.65 550.46,1194.69 554.63,1194.69 574.92,1214.98 587.25,1214.98 599.98,1202.26 599.98,1189.93 550.16,1140.11 550.16,1135.94 557.12,1128.98 559.29,1128.98 587.79,1157.48 602.5,1157.48 614.17,1145.81 614.17,1131.75 595.81,1113.39 573.55,1091.13 573.55,1086.95 580.51,1079.99 582.68,1079.99 607.03,1104.33 620.22,1104.33 633.86,1090.69 633.86,1078.6 613.19,1057.93 613.19,1054.2 621.45,1045.94 624.68,1045.94 635.83,1057.09 639.76,1057.09 647.64,1049.21 647.64,1045.12 639.76,1037.24 639.76,1027.63 718.57,948.82 2021.65,948.82 2261.81,1188.98 2295.28,1188.98 2671.12,1188.98 2877.95,1395.81 2877.95,2223.5 2971.19,2316.73 3046.26,2316.73 3049.21,2319.69 U33.142@3074.8,2319.69
  Bottom w3.94: v1(354.33,1263.78) 360.24,1269.69 555.12,1269.69 v1(561.02,1263.78)
MIPI_DPHY_CSI1_RX_D0N: J10.14 U33.128 | length 4645.8
  Top w3.94: J10.14@86.61,1622.05 116.14,1622.05 129.92,1608.27 154.6,1608.27 204.72,1558.14 204.72,1457.37 280.2,1381.89 348.43,1381.89 v1(354.33,1387.8) ; v1(486.22,1387.8) 480.31,1381.89 466.54,1381.89 450.79,1366.14 450.79,1084.65 665.35,870.08 2057.23,870.08 2283.6,1096.46 2710.63,1096.46 2962.6,1348.43 2962.6,2175.2 2999.8,2212.4 3046.26,2212.4 3049.21,2209.45 U33.128@3074.8,2209.45
  Bottom w3.94: v1(354.33,1387.8) 360.24,1381.89 480.31,1381.89 v1(486.22,1387.8)
MIPI_DPHY_CSI1_RX_D0P: J10.13 U33.130 | length 4650.2
  Top w3.94: J10.13@86.61,1582.68 116.14,1582.68 131.89,1598.43 150.52,1598.43 192.91,1556.03 192.91,1549.21 190.94,1547.24 183.07,1547.24 178.91,1543.08 178.91,1534.03 181.86,1531.08 190.01,1531.08 192.97,1528.13 192.97,1518.29 190.01,1515.33 184.82,1515.33 181.87,1512.38 181.87,1502.54 184.82,1499.59 189.96,1499.59 194.88,1494.66 194.88,1453.29 276.13,1372.05 348.43,1372.05 v1(354.33,1366.14) ; v1(486.22,1366.14) 480.31,1372.05 470.61,1372.05 460.63,1362.07 460.63,1088.72 669.43,879.92 2053.15,879.92 2279.53,1106.3 2322.83,1106.3 2706.55,1106.3 2952.76,1352.5 2952.76,2152.63 2952.76,2179.27 2995.73,2222.24 3046.26,2222.24 3049.21,2225.2 U33.130@3074.8,2225.2
  Bottom w3.94: v1(354.33,1366.14) 360.24,1372.05 480.31,1372.05 v1(486.22,1366.14)
MIPI_DPHY_CSI1_RX_D1N: J10.11 U33.134 | length 4650.4
  Top w3.94: J10.11@86.61,1503.94 122.05,1503.94 136.81,1489.17 155.58,1489.17 167.32,1477.43 167.32,1403.54 199.8,1371.06 244.23,1371.06 253.94,1361.36 253.94,1314.96 257.87,1311.02 265.75,1311.02 269.69,1314.96 269.69,1343.64 277.42,1351.38 295.42,1351.38 304.13,1342.66 304.13,1331.69 307.09,1328.74 370.08,1328.74 v1(375.98,1334.65) ; v1(525.59,1334.65) 519.69,1328.74 503.94,1328.74 485.24,1310.04 485.24,1242.06 500.98,1226.31 500.98,1210.77 487.2,1196.99 487.2,1176.64 506.89,1156.95 506.89,1147.11 489.63,1129.85 489.63,1100.92 685.04,905.51 2041.48,905.51 2273.76,1137.8 2698.82,1137.8 2925.2,1364.17 2925.2,2198.82 2986.02,2259.65 3046.26,2259.65 3049.21,2256.69 U33.134@3074.8,2256.69
  Bottom w3.94: v1(375.98,1334.65) 381.89,1328.74 519.69,1328.74 v1(525.59,1334.65)
MIPI_DPHY_CSI1_RX_D1P: J10.10 U33.136 | length 4637.5
  Top w3.94: J10.10@86.61,1464.57 122.05,1464.57 136.81,1479.33 151.5,1479.33 157.48,1473.36 157.48,1414.3 157.48,1399.47 195.73,1361.22 240.16,1361.22 243.11,1358.27 243.11,1311.87 253.8,1301.18 269.82,1301.18 279.53,1310.88 279.53,1339.57 281.5,1341.54 291.34,1341.54 294.29,1338.58 294.29,1327.62 303.01,1318.9 370.08,1318.9 v1(375.98,1312.99) ; v1(525.59,1312.99) 519.69,1318.9 508.01,1318.9 495.08,1305.96 495.08,1292.08 498.03,1289.12 505.61,1289.12 508.56,1286.17 508.56,1276.33 505.61,1273.38 498.47,1273.38 495.08,1269.98 495.08,1246.13 510.83,1230.38 510.83,1206.69 497.05,1192.91 497.05,1180.72 516.73,1161.03 516.73,1143.03 499.47,1125.77 499.47,1105 689.12,915.35 2037.4,915.35 2269.68,1147.64 2311.02,1147.64 2694.74,1147.64 2915.35,1368.25 2915.35,2193.97 2915.35,2202.9 2981.95,2269.49 3046.26,2269.49 3049.21,2272.44 U33.136@3074.8,2272.44
  Bottom w3.94: v1(375.98,1312.99) 381.89,1318.9 519.69,1318.9 v1(525.59,1312.99)
MIPI_DPHY_CSI2_CAM_CLKOUT: J11.22 U33.41 | length 4117
  Top w3.94: J11.22@1193.7,1977.56 1244.09,1927.17 v1(1244.09,1620.08) ; v1(4480.32,2312.99) 4487.01,2319.69 U33.41@4520.08,2319.69
  Bottom w3.94: v1(1244.09,1620.08) 1891.73,1620.08 2100.39,1411.42 2685.04,1411.42 2994.09,1720.47 3683.07,1720.47 4255.91,2293.31 4413.39,2293.31 4423.23,2303.15 4470.47,2303.15 v1(4480.32,2312.99)
MIPI_DPHY_CSI2_RX_CLKN: J9.8 U33.169 | length 5398
  Top w3.94: J9.8@86.61,545.28 122.05,545.28 136.81,530.51 149.47,530.51 239.95,620.99 239.95,626.99 236.1,630.83 236.1,635.01 243.06,641.97 247.23,641.97 251.51,637.69 255.69,637.69 262.65,644.65 262.65,648.83 258.64,652.84 258.64,657.02 265.6,663.98 269.77,663.98 274.26,659.48 278.44,659.48 302.03,683.07 335.56,683.07 2100.39,683.07 2368.11,950.79 3318.9,950.79 3513.78,1145.67 3513.78,2444.74 3415.41,2543.11 3207.68,2543.11 3204.72,2540.16 U33.169@3178.74,2540.16
MIPI_DPHY_CSI2_RX_CLKP: J9.7 U33.171 | length 5396.8
  Top w3.94: J9.7@86.61,505.91 122.05,505.91 136.81,520.67 153.54,520.67 306.1,673.23 2061.02,673.23 2104.47,673.23 2372.19,940.95 3322.97,940.95 3523.62,1141.59 3523.62,1211.54 3523.62,2403.54 3523.62,2448.82 3419.49,2552.95 3207.68,2552.95 3204.72,2555.91 U33.171@3178.74,2555.91
MIPI_DPHY_CSI2_RX_D0N: J9.14 U33.157 | length 5402.7
  Top w3.94: J9.14@86.61,781.5 125.98,781.5 139.76,767.72 157.48,767.72 159.45,769.69 159.45,781.5 161.42,783.46 173.23,783.46 177.17,779.53 177.17,681.1 180.12,678.15 189.96,678.15 192.91,681.1 192.91,758.01 201.63,766.73 219.63,766.73 228.35,758.01 228.35,736.22 231.3,733.27 241.14,733.27 244.09,736.22 244.09,759.98 252.81,768.7 2084.51,768.7 2324.07,1008.26 3259.18,1008.26 3282.79,1031.87 3306.41,1031.87 3313.37,1038.83 3313.37,1043.01 3303.91,1052.47 3303.91,1064.8 3316.63,1077.53 3328.96,1077.53 3338.43,1068.07 3342.6,1068.07 3349.56,1075.03 3349.56,1079.2 3340.1,1088.66 3340.1,1100.99 3352.82,1113.72 3365.15,1113.72 3372.65,1106.22 3376.82,1106.22 3383.78,1113.18 3383.78,1117.36 3377.27,1123.87 3377.27,1136.2 3390,1148.93 3402.33,1148.93 3409.82,1141.43 3414,1141.43 3420.96,1148.39 3420.96,1152.57 3413.46,1160.06 3413.46,1172.39 3438.98,1197.9 3438.98,2411.42 3401.77,2448.62 3207.68,2448.62 3204.72,2445.67 U33.157@3178.74,2445.67
MIPI_DPHY_CSI2_RX_D0P: J9.13 U33.159 | length 5402.7
  Top w3.94: J9.13@86.61,742.13 120.08,742.13 134.85,756.89 164.37,756.89 167.32,753.94 167.32,677.03 176.04,668.31 194.04,668.31 202.76,677.03 202.76,753.94 205.71,756.89 215.55,756.89 218.5,753.94 218.5,732.14 227.22,723.43 245.22,723.43 253.94,732.14 253.94,755.91 256.89,758.86 2088.58,758.86 2328.14,998.42 3263.25,998.42 3286.87,1022.03 3308.42,1022.03 ; U33.159@3178.74,2461.42 3204.72,2461.42 3207.68,2458.46 3405.85,2458.46 3448.82,2415.49 3448.82,1193.83 3423.31,1168.31 3423.31,1164.14 3430.8,1156.64 3430.8,1144.31 3418.08,1131.59 3416.04,1131.59 ; 3308.45,1022.03 3310.49,1022.03 3323.21,1034.76 3323.21,1047.09 3313.75,1056.55 3313.75,1060.73 3320.71,1067.69 3324.89,1067.69 3334.32,1058.25 3336.35,1058.22 3344.61,1058.22 ; 3344.64,1058.22 3346.68,1058.22 3359.4,1070.95 3359.4,1083.28 3349.94,1092.74 3349.94,1096.92 3356.9,1103.88 3361.08,1103.88 3368.55,1096.41 3370.58,1096.38 3378.83,1096.38 3380.9,1096.38 3393.63,1109.11 3393.63,1121.44 3387.11,1127.95 3387.11,1132.12 3394.07,1139.08 3398.25,1139.08 3405.72,1131.61 3407.75,1131.59 3416,1131.59
MIPI_DPHY_CSI2_RX_D1N: J9.11 U33.163 | length 5397.9
  Top w3.94: J9.11@86.61,663.39 122.05,663.39 136.81,648.62 202.62,648.62 285.29,731.3 2097.44,731.3 2348.43,982.28 3297.1,982.28 3476.38,1161.56 3476.38,2434.9 3464.95,2446.32 3460.78,2446.32 3456.01,2441.55 3451.83,2441.55 3444.87,2448.51 3444.87,2452.69 3448.13,2455.95 3448.13,2460.12 3417.11,2491.14 3381.55,2491.14 3372.83,2499.86 3372.83,2513.78 3369.88,2516.73 3360.04,2516.73 3357.09,2513.78 3357.09,2482.14 3348.37,2473.43 3330.37,2473.43 3321.65,2482.14 3321.65,2511.81 3318.7,2514.76 3308.86,2514.76 3305.91,2511.81 3305.91,2480.18 3297.19,2471.46 3279.19,2471.46 3270.47,2480.18 3270.47,2513.78 3267.52,2516.73 3257.68,2516.73 3254.72,2513.78 3254.72,2504.58 3246.01,2495.87 3207.68,2495.87 3204.72,2492.91 U33.163@3178.74,2492.91
MIPI_DPHY_CSI2_RX_D1P: J9.10 U33.165 | length 5415.1
  Top w3.94: J9.10@86.61,624.02 122.05,624.02 136.81,638.78 206.69,638.78 289.37,721.46 2101.52,721.46 2352.5,972.44 3301.18,972.44 3486.22,1157.48 3486.22,1252.88 3486.22,2387.8 3486.22,2438.98 3424.21,2500.98 3385.63,2500.98 3382.68,2503.94 3382.68,2517.86 3373.96,2526.57 3355.96,2526.57 3347.24,2517.86 3347.24,2486.22 3344.29,2483.27 3334.45,2483.27 3331.5,2486.22 3331.5,2515.89 3322.78,2524.61 3304.78,2524.61 3296.06,2515.89 3296.06,2484.25 3293.11,2481.3 3283.27,2481.3 3280.31,2484.25 3280.31,2517.86 3271.6,2526.57 3253.6,2526.57 3244.88,2517.86 3244.88,2508.66 3241.93,2505.71 3207.68,2505.71 3204.72,2508.66 U33.165@3178.74,2508.66
MIPI_DPHY_CSI3_RX_CLKN: J16.17 U33.127 | length 4009.7
  Top w3.94: v1(586.61,3285.43) 598.42,3297.24 J16.17@598.42,3332.68 ; U33.127@3178.74,2209.45 3204.72,2209.45 3207.68,2212.4 3224.41,2212.4 3236.22,2224.21 3236.22,2330.71 3248.03,2342.52 3301.18,2342.52 3311.02,2332.68 3352.36,2332.68 v1(3358.27,2326.77)
  Bottom w3.94: v1(586.61,3285.43) 582.68,3289.37 582.68,3320.73 624.16,3362.2 799.07,3362.2 988.19,3173.09 988.19,2771.51 1112.06,2647.64 1539.37,2647.64 2978.49,2647.64 3013.92,2683.07 3142.72,2683.07 3187.99,2637.8 3236.08,2637.8 3348.43,2525.45 3348.43,2417.67 3344.14,2413.39 3339.06,2413.39 3336.11,2410.43 3336.11,2400.59 3339.06,2397.64 3345.47,2397.64 3348.43,2394.69 3348.43,2361.22 3344.49,2357.28 3344.49,2340.55 v1(3358.27,2326.77)
MIPI_DPHY_CSI3_RX_CLKP: J16.18 U33.129 | length 4014.2
  Top w3.94: J16.18@586.61,3219.5 586.61,3251.97 v1(586.61,3263.78) ; U33.129@3178.74,2225.2 3204.72,2225.2 3207.68,2222.24 3220.33,2222.24 3226.38,2228.29 3226.38,2334.79 3243.95,2352.36 3303.15,2352.36 3305.26,2352.36 3315.1,2342.52 3352.36,2342.52 v1(3358.27,2348.43)
  Bottom w3.94: v1(586.61,3263.78) 572.83,3277.56 572.83,3324.8 620.08,3372.05 803.15,3372.05 998.03,3177.17 998.03,2775.59 1116.14,2657.48 2974.41,2657.48 3009.84,2692.91 3146.79,2692.91 3192.07,2647.64 3240.16,2647.64 3358.27,2529.53 v1(3358.27,2348.43)
MIPI_DPHY_CSI3_RX_D0N: J16.14 U33.115 | length 4000.8
  Top w3.94: v1(622.05,3263.78) 633.86,3251.97 J16.14@633.86,3219.5 ; U33.115@3178.74,2114.96 3204.72,2114.96 3207.68,2117.91 3244.09,2117.91 3316.93,2190.75 3316.93,2287.4 v1(3322.83,2293.31)
  Bottom w3.94: v1(622.05,3263.78) 608.27,3277.56 608.27,3312.99 637.8,3342.52 787.54,3342.52 962.6,3167.46 962.6,2758.01 1105.45,2615.16 2833.2,2615.16 2845.02,2603.35 2847.9,2603.35 2850.85,2606.3 2850.85,2616.28 2859.57,2625 2877.57,2625 2886.28,2616.28 2886.28,2606.3 2889.24,2603.35 2899.08,2603.35 2902.03,2606.3 2902.03,2616.28 2910.75,2625 2928.75,2625 2937.46,2616.28 2937.46,2606.3 2940.42,2603.35 2950.26,2603.35 2953.21,2606.3 2953.21,2608.86 2961.93,2617.58 2989.63,2617.58 3019.68,2647.64 3132.03,2647.64 3179.27,2600.39 3226.38,2600.39 3316.93,2509.84 3316.93,2299.21 v1(3322.83,2293.31)
MIPI_DPHY_CSI3_RX_D0P: J16.15 U33.117 | length 4008.7
  Top w3.94: v1(622.05,3285.43) 622.05,3299.49 J16.15@622.05,3332.68 ; U33.117@3178.74,2130.71 3204.72,2130.71 3207.68,2127.76 3240.02,2127.76 3307.09,2194.82 3307.09,2287.4 v1(3301.18,2293.31)
  Bottom w3.94: v1(622.05,3285.43) 618.11,3289.37 618.11,3308.92 641.87,3332.68 783.46,3332.68 952.76,3163.39 952.76,2753.94 1101.38,2605.32 2829.13,2605.32 2840.94,2593.5 2851.98,2593.5 2860.69,2602.22 2860.69,2612.2 2863.65,2615.16 2873.49,2615.16 2876.44,2612.2 2876.44,2602.22 2885.16,2593.5 2903.16,2593.5 2911.87,2602.22 2911.87,2612.2 2914.83,2615.16 2924.67,2615.16 2927.62,2612.2 2927.62,2602.22 2936.34,2593.5 2954.34,2593.5 2963.06,2602.22 2963.06,2604.79 2966.01,2607.74 2993.71,2607.74 3023.76,2637.8 3127.95,2637.8 3175.2,2590.55 3222.3,2590.55 3259.71,2553.14 3259.71,2548.29 3255.5,2544.08 3255.5,2539.9 3262.46,2532.94 3266.64,2532.94 3270.12,2536.43 3274.3,2536.43 3281.26,2529.47 3281.26,2525.29 3278.58,2522.61 3278.58,2518.44 3285.54,2511.48 3289.71,2511.48 3293.46,2515.22 3297.63,2515.22 3307.09,2505.77 3306.95,2505.63 3306.95,2471.46 3304,2468.5 3297.32,2468.5 3294.37,2465.55 3294.37,2455.71 3297.32,2452.76 3304,2452.76 3306.95,2449.8 3306.95,2439.96 3304,2437.01 3297.32,2437.01 3294.37,2434.06 3294.37,2424.21 3297.32,2421.26 3303.94,2421.26 3306.9,2418.31 3306.9,2408.46 3303.94,2405.51 3297.44,2405.51 3294.49,2402.56 3294.49,2392.72 3297.44,2389.76 3304.13,2389.76 3307.09,2386.81 3307.09,2328.4 3307.09,2299.21 v1(3301.18,2293.31)
MIPI_DPHY_CSI3_RX_D1N: J16.11 U33.121 | length 4006.9
  Top w3.94: v1(657.48,3285.43) 669.29,3297.24 J16.11@669.29,3332.68 ; U33.121@3178.74,2162.2 3204.72,2162.2 3208.24,2165.72 3232.85,2165.72 3277.56,2210.43 3277.56,2301.18 v1(3263.78,2314.96)
  Bottom w3.94: v1(657.48,3285.43) 658.39,3286.35 653.54,3291.2 653.54,3299.07 659.59,3305.12 765.61,3305.12 915.35,3155.37 915.35,2736.08 1086.47,2564.96 3008.01,2564.96 3036.56,2593.5 3078.74,2593.5 3081.69,2590.55 3081.69,2570.73 3090.41,2562.01 3108.41,2562.01 3117.13,2570.73 3117.13,2588.58 3120.08,2591.54 3129.92,2591.54 3132.87,2588.58 3132.87,2548.09 3141.59,2539.37 3222.44,2539.37 3225.39,2536.42 3225.39,2515.75 3218.5,2508.86 3169.22,2508.86 3156.5,2496.13 3156.5,2468.43 3173.16,2451.77 3220.47,2451.77 3230.32,2441.93 3230.32,2405.51 3223.43,2398.62 3196.78,2398.62 3184.06,2385.9 3184.06,2354.19 3197.69,2340.55 3209.65,2340.55 3212.6,2337.6 3212.6,2327.29 3215.55,2324.34 3225.39,2324.34 3228.35,2327.29 3228.35,2337.61 3231.29,2340.55 3266.66,2340.55 3271.65,2335.56 3271.65,2330.71 3263.78,2322.83 v1(3263.78,2314.96)
MIPI_DPHY_CSI3_RX_D1P: J16.12 U33.123 | length 4015.4
  Top w3.94: J16.12@657.48,3219.5 657.48,3251.97 v1(657.48,3263.78) ; U33.123@3178.74,2177.95 3204.72,2177.95 3207.12,2175.56 3228.77,2175.56 3267.72,2214.51 3267.72,2289.37 v1(3263.78,2293.31)
  Bottom w3.94: v1(657.48,3263.78) 643.7,3277.56 643.7,3303.15 655.51,3314.96 769.69,3314.96 925.2,3159.45 925.2,2740.16 1090.55,2574.8 3003.94,2574.8 3032.48,2603.35 3082.82,2603.35 3091.54,2594.63 3091.54,2574.8 3094.49,2571.85 3104.33,2571.85 3107.28,2574.8 3107.28,2592.66 3116,2601.38 3134,2601.38 3142.72,2592.66 3142.72,2552.17 3145.67,2549.21 3226.52,2549.21 3235.24,2540.49 3235.24,2511.67 3222.58,2499.02 3173.3,2499.02 3166.34,2492.06 3166.34,2472.51 3177.24,2461.61 3224.55,2461.61 3240.16,2446.01 3240.16,2399.61 3229.33,2388.78 3200.86,2388.78 3193.9,2381.82 3193.9,2358.27 3201.77,2350.39 3270.74,2350.39 3281.5,2339.64 3281.5,2325.62 3277.56,2321.68 3277.56,2307.09 v1(3263.78,2293.31)
MIPI_DPHY_CSI4_RX_CLKN: J16.8 U33.104 | length 3399.3
  Top w3.94: v1(692.91,3263.78) 704.72,3251.97 J16.8@704.72,3219.5 ; v1(2994.09,2125.98) 3000,2120.08 3000,2043.24 3019.81,2023.43 3046.26,2023.43 3049.21,2020.47 U33.104@3074.8,2020.47
  Bottom w3.94: v1(692.91,3263.78) 688.98,3259.84 688.98,3218.5 704.72,3202.76 704.72,2679.27 1087.74,2296.26 2444.04,2296.26 2537.54,2202.76 2878.09,2202.76 2903.16,2177.69 2907.33,2177.69 2910.95,2181.31 2915.12,2181.31 2922.08,2174.35 2922.08,2170.17 2919.09,2167.18 2919.09,2163.01 2926.05,2156.05 2930.23,2156.05 2933,2158.82 2937.18,2158.82 2944.14,2151.86 2944.14,2147.68 2941.46,2145 2941.46,2140.83 2948.42,2133.87 2952.59,2133.87 2955.23,2136.51 2959.41,2136.51 2966.37,2129.55 2966.37,2125.38 2963.73,2122.73 2963.73,2117.12 2972.58,2108.27 2993.95,2108.27 3000,2114.31 3000,2120.08 v1(2994.09,2125.98)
